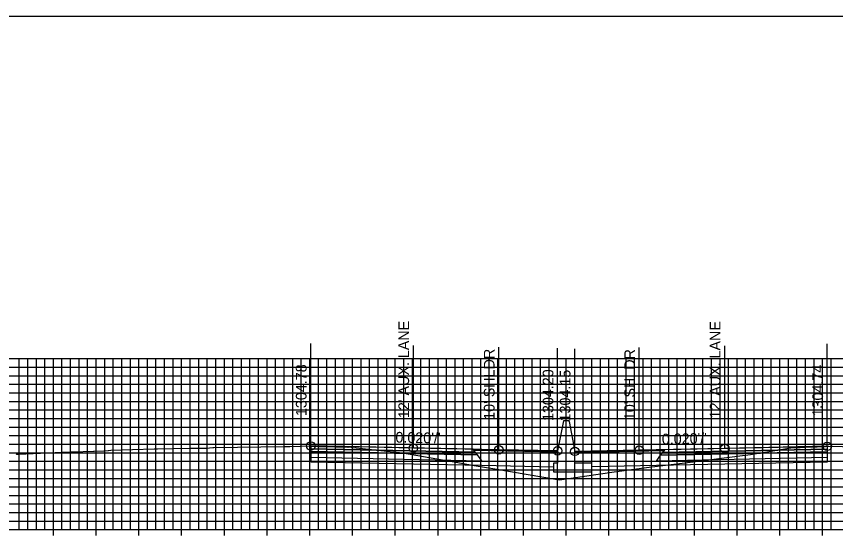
# Model space of a CAD drawing. Extents: x 674939 to 678919, y 750652 to 765176.
# Drawn here: x 678674.2 to 678770.1, y 754071.5 to 754132.6 of the extents above; entities that cross this region are included whole.
import ezdxf

# ---------------------------------------------------------------- set-up
doc = ezdxf.new("R2010")
doc.units = 0
for name, color, linetype in [('R_Alt Surface', 7, 'Continuous'), ('R_Axis', 7, 'Continuous'), ('R_Exist Surface', 7, 'Continuous'), ('R_Fin Surface', 7, 'Continuous'), ('R_Grid', 7, 'Continuous'), ('R_No Plot', 7, 'Continuous'), ('R_Proposed Road', 7, 'Continuous'), ('R_Xsect Elev', 7, 'Continuous'), ('R_Xsect Slope', 7, 'Continuous')]:
    doc.layers.add(name, color=color, linetype=linetype)

msp = doc.modelspace()

# ---------------------------------------------------------------- linework, layer by layer
at = {"layer": 'R_Alt Surface'}
for points in [[(678708.65, 754082.001), (678708.65, 754081.671), (678728.15, 754081.281), (678727.9, 754081.616)], [(678769.088, 754081.963), (678769.088, 754081.633), (678749.588, 754081.243), (678749.838, 754081.578)], [(678708.65, 754081.671), (678708.65, 754081.011), (678728.65, 754080.611), (678728.15, 754081.281)], [(678769.088, 754081.633), (678769.088, 754080.973), (678749.088, 754080.573), (678749.588, 754081.243)]]:
    msp.add_lwpolyline(points, close=True, dxfattribs=at)
for points in [[(678708.65, 754081.011), (678708.65, 754080.471), (678728.65, 754080.071), (678737.033, 754079.904)], [(678769.088, 754080.973), (678769.088, 754080.433), (678749.088, 754080.033), (678741.533, 754079.882)]]:
    msp.add_lwpolyline(points, dxfattribs=at)
at = {"layer": 'R_Axis'}
for p, q in [((678678.533, 754071.851), (678678.533, 754073.251)), ((678683.533, 754071.851), (678683.533, 754073.251)), ((678688.533, 754071.851), (678688.533, 754073.251)), ((678693.533, 754071.851), (678693.533, 754073.251)), ((678698.533, 754071.851), (678698.533, 754073.251)), ((678703.533, 754071.851), (678703.533, 754073.251)), ((678708.533, 754071.851), (678708.533, 754073.251)), ((678713.533, 754071.851), (678713.533, 754073.251)), ((678718.533, 754071.851), (678718.533, 754073.251)), ((678723.533, 754071.851), (678723.533, 754073.251)), ((678728.533, 754071.851), (678728.533, 754073.251)), ((678733.533, 754071.851), (678733.533, 754073.251)), ((678738.533, 754071.851), (678738.533, 754073.251)), ((678743.533, 754071.851), (678743.533, 754073.251)), ((678748.533, 754071.851), (678748.533, 754073.251)), ((678753.533, 754071.851), (678753.533, 754073.251)), ((678758.533, 754071.851), (678758.533, 754073.251)), ((678763.533, 754071.851), (678763.533, 754073.251)), ((678768.533, 754071.851), (678768.533, 754073.251)), ((678638.533, 754072.551), (678838.533, 754072.551))]:
    msp.add_line(p, q, dxfattribs=at)
at = {"layer": 'R_Exist Surface'}
msp.add_lwpolyline([(678674.16, 754081.354), (678674.226, 754081.365), (678674.241, 754081.368), (678674.429, 754081.376), (678680.454, 754081.652), (678680.63, 754081.66), (678680.771, 754081.664), (678683.218, 754081.741), (678683.3, 754081.742), (678684.429, 754081.765), (678684.46, 754081.768), (678684.955, 754081.807), (678684.971, 754081.809), (678685.23, 754081.829), (678690.311, 754081.983), (678690.701, 754081.994), (678694.465, 754082.064), (678694.737, 754082.069), (678696.431, 754082.096), (678696.806, 754082.1), (678697.183, 754082.142), (678697.289, 754082.147), (678705.568, 754082.275), (678706.184, 754082.285), (678708.631, 754082.332), (678708.633, 754082.332), (678708.65, 754082.331), (678708.696, 754082.329), (678709.619, 754082.272), (678709.678, 754082.271), (678710.242, 754082.262), (678710.619, 754082.283), (678711.56, 754082.235), (678711.654, 754082.234), (678712.031, 754082.243), (678712.972, 754082.21), (678713.031, 754082.207), (678713.034, 754082.208), (678713.1, 754082.228), (678713.61, 754082.17), (678719.372, 754081.542), (678725.872, 754080.384), (678727.766, 754080.054), (678730.193, 754079.647), (678737.761, 754078.367), (678743.886, 754079.266), (678747.916, 754079.81), (678752.422, 754080.379), (678760.096, 754081.337), (678763.89, 754081.954), (678765.065, 754082.149), (678765.106, 754082.141), (678765.616, 754082.173), (678765.895, 754082.163), (678766.498, 754082.185), (678767.196, 754082.218), (678767.476, 754082.21), (678767.898, 754082.222), (678768.736, 754082.257), (678768.886, 754082.266), (678769.088, 754082.293), (678769.165, 754082.303), (678769.257, 754082.308), (678772.472, 754082.252)], dxfattribs=at)
at = {"layer": 'R_Fin Surface'}
for points in [[(678737.533, 754081.754), (678730.65, 754081.891), (678720.65, 754082.091), (678708.65, 754082.331)], [(678769.088, 754082.293), (678757.088, 754082.053), (678747.088, 754081.853), (678739.533, 754081.702)]]:
    msp.add_lwpolyline(points, dxfattribs=at)
for points in [[(678708.65, 754082.331), (678708.65, 754082.001), (678727.9, 754081.616), (678727.65, 754081.951)], [(678727.65, 754081.951), (678737.533, 754081.754), (678737.537, 754081.596), (678727.769, 754081.791)], [(678749.969, 754081.753), (678739.533, 754081.544), (678739.533, 754081.702), (678750.088, 754081.913)], [(678769.088, 754082.293), (678769.088, 754081.963), (678749.838, 754081.578), (678750.088, 754081.913)]]:
    msp.add_lwpolyline(points, close=True, dxfattribs=at)
at = {"layer": 'R_Grid'}
for p, q in [((678638.533, 754092.551), (678838.533, 754092.551)), ((678674.533, 754072.551), (678674.533, 754092.551)), ((678675.533, 754072.551), (678675.533, 754092.551)), ((678676.533, 754072.551), (678676.533, 754092.551)), ((678677.533, 754072.551), (678677.533, 754092.551)), ((678678.533, 754072.551), (678678.533, 754092.551)), ((678679.533, 754072.551), (678679.533, 754092.551)), ((678680.533, 754072.551), (678680.533, 754092.551)), ((678681.533, 754072.551), (678681.533, 754092.551)), ((678682.533, 754072.551), (678682.533, 754092.551)), ((678683.533, 754072.551), (678683.533, 754092.551)), ((678684.533, 754072.551), (678684.533, 754092.551)), ((678685.533, 754072.551), (678685.533, 754092.551)), ((678686.533, 754072.551), (678686.533, 754092.551)), ((678687.533, 754072.551), (678687.533, 754092.551)), ((678688.533, 754072.551), (678688.533, 754092.551)), ((678689.533, 754072.551), (678689.533, 754092.551)), ((678690.533, 754072.551), (678690.533, 754092.551)), ((678691.533, 754072.551), (678691.533, 754092.551)), ((678692.533, 754072.551), (678692.533, 754092.551)), ((678693.533, 754072.551), (678693.533, 754092.551)), ((678694.533, 754072.551), (678694.533, 754092.551)), ((678695.533, 754072.551), (678695.533, 754092.551)), ((678696.533, 754072.551), (678696.533, 754092.551)), ((678697.533, 754072.551), (678697.533, 754092.551)), ((678698.533, 754072.551), (678698.533, 754092.551)), ((678699.533, 754072.551), (678699.533, 754092.551)), ((678700.533, 754072.551), (678700.533, 754092.551)), ((678701.533, 754072.551), (678701.533, 754092.551)), ((678702.533, 754072.551), (678702.533, 754092.551)), ((678703.533, 754072.551), (678703.533, 754092.551)), ((678704.533, 754072.551), (678704.533, 754092.551)), ((678705.533, 754072.551), (678705.533, 754092.551)), ((678706.533, 754072.551), (678706.533, 754092.551)), ((678707.533, 754072.551), (678707.533, 754092.551)), ((678708.533, 754072.551), (678708.533, 754092.551)), ((678709.533, 754072.551), (678709.533, 754092.551)), ((678710.533, 754072.551), (678710.533, 754092.551)), ((678711.533, 754072.551), (678711.533, 754092.551)), ((678712.533, 754072.551), (678712.533, 754092.551)), ((678713.533, 754072.551), (678713.533, 754092.551)), ((678714.533, 754072.551), (678714.533, 754092.551)), ((678715.533, 754072.551), (678715.533, 754092.551)), ((678716.533, 754072.551), (678716.533, 754092.551)), ((678717.533, 754072.551), (678717.533, 754092.551)), ((678718.533, 754072.551), (678718.533, 754092.551)), ((678719.533, 754072.551), (678719.533, 754092.551)), ((678720.533, 754072.551), (678720.533, 754092.551)), ((678721.533, 754072.551), (678721.533, 754092.551)), ((678722.533, 754072.551), (678722.533, 754092.551)), ((678723.533, 754072.551), (678723.533, 754092.551)), ((678724.533, 754072.551), (678724.533, 754092.551)), ((678725.533, 754072.551), (678725.533, 754092.551)), ((678726.533, 754072.551), (678726.533, 754092.551)), ((678727.533, 754072.551), (678727.533, 754092.551)), ((678728.533, 754072.551), (678728.533, 754092.551)), ((678729.533, 754072.551), (678729.533, 754092.551)), ((678730.533, 754072.551), (678730.533, 754092.551)), ((678731.533, 754072.551), (678731.533, 754092.551)), ((678732.533, 754072.551), (678732.533, 754092.551)), ((678733.533, 754072.551), (678733.533, 754092.551)), ((678734.533, 754072.551), (678734.533, 754092.551)), ((678735.533, 754072.551), (678735.533, 754092.551)), ((678736.533, 754072.551), (678736.533, 754092.551)), ((678737.533, 754072.551), (678737.533, 754092.551)), ((678738.533, 754072.551), (678738.533, 754092.551)), ((678739.533, 754072.551), (678739.533, 754092.551)), ((678740.533, 754072.551), (678740.533, 754092.551)), ((678741.533, 754072.551), (678741.533, 754092.551)), ((678742.533, 754072.551), (678742.533, 754092.551)), ((678743.533, 754072.551), (678743.533, 754092.551)), ((678744.533, 754072.551), (678744.533, 754092.551)), ((678745.533, 754072.551), (678745.533, 754092.551)), ((678746.533, 754072.551), (678746.533, 754092.551)), ((678747.533, 754072.551), (678747.533, 754092.551)), ((678748.533, 754072.551), (678748.533, 754092.551)), ((678749.533, 754072.551), (678749.533, 754092.551)), ((678750.533, 754072.551), (678750.533, 754092.551)), ((678751.533, 754072.551), (678751.533, 754092.551)), ((678752.533, 754072.551), (678752.533, 754092.551)), ((678753.533, 754072.551), (678753.533, 754092.551)), ((678754.533, 754072.551), (678754.533, 754092.551)), ((678755.533, 754072.551), (678755.533, 754092.551)), ((678756.533, 754072.551), (678756.533, 754092.551)), ((678757.533, 754072.551), (678757.533, 754092.551)), ((678758.533, 754072.551), (678758.533, 754092.551)), ((678759.533, 754072.551), (678759.533, 754092.551)), ((678760.533, 754072.551), (678760.533, 754092.551)), ((678761.533, 754072.551), (678761.533, 754092.551)), ((678762.533, 754072.551), (678762.533, 754092.551)), ((678763.533, 754072.551), (678763.533, 754092.551)), ((678764.533, 754072.551), (678764.533, 754092.551)), ((678765.533, 754072.551), (678765.533, 754092.551)), ((678766.533, 754072.551), (678766.533, 754092.551)), ((678767.533, 754072.551), (678767.533, 754092.551)), ((678768.533, 754072.551), (678768.533, 754092.551)), ((678769.533, 754072.551), (678769.533, 754092.551)), ((678638.533, 754091.551), (678838.533, 754091.551)), ((678638.533, 754090.551), (678838.533, 754090.551)), ((678638.533, 754089.551), (678838.533, 754089.551)), ((678638.533, 754088.551), (678838.533, 754088.551)), ((678638.533, 754087.551), (678838.533, 754087.551)), ((678638.533, 754086.551), (678838.533, 754086.551)), ((678638.533, 754085.551), (678838.533, 754085.551)), ((678638.533, 754084.551), (678838.533, 754084.551)), ((678638.533, 754083.551), (678838.533, 754083.551)), ((678638.533, 754082.551), (678838.533, 754082.551)), ((678638.533, 754081.551), (678838.533, 754081.551)), ((678638.533, 754080.551), (678838.533, 754080.551)), ((678638.533, 754079.551), (678838.533, 754079.551)), ((678638.533, 754078.551), (678838.533, 754078.551)), ((678638.533, 754077.551), (678838.533, 754077.551)), ((678638.533, 754076.551), (678838.533, 754076.551)), ((678638.533, 754075.551), (678838.533, 754075.551)), ((678638.533, 754074.551), (678838.533, 754074.551)), ((678638.533, 754073.551), (678838.533, 754073.551)), ((678638.533, 754072.551), (678838.533, 754072.551))]:
    msp.add_line(p, q, dxfattribs=at)
at = {"layer": 'R_No Plot'}
msp.add_lwpolyline([(678578.533, 753912.551), (678918.533, 753912.551), (678918.533, 754132.551), (678578.533, 754132.551)], close=True, dxfattribs=at)
for centre in [(678708.65, 754082.331), (678769.088, 754082.293), (678720.65, 754082.091), (678730.65, 754081.891), (678737.533, 754081.754), (678739.533, 754081.702), (678747.088, 754081.853), (678757.088, 754082.053)]:
    msp.add_circle(centre, 0.5, dxfattribs=at)
at = {"layer": 'R_Proposed Road'}
for points in [[(678738.203, 754085.254), (678737.533, 754081.754)], [(678738.863, 754085.202), (678738.863, 754085.254), (678738.203, 754085.254), (678738.203, 754085.254)], [(678738.863, 754085.202), (678739.533, 754081.702)], [(678737.533, 754081.754), (678737.533, 754080.327), (678737.033, 754080.327), (678737.033, 754079.327), (678741.533, 754079.327), (678741.533, 754080.327), (678739.533, 754080.327), (678739.533, 754081.702)]]:
    msp.add_lwpolyline(points, dxfattribs=at)
at = {"layer": 'R_Xsect Elev'}
for p, q in [((678708.65, 754082.331), (678708.65, 754094.331)), ((678769.088, 754082.293), (678769.088, 754094.293)), ((678720.65, 754082.091), (678720.65, 754094.091)), ((678730.65, 754081.891), (678730.65, 754093.891)), ((678737.533, 754081.754), (678737.533, 754093.754)), ((678739.533, 754081.702), (678739.533, 754093.702)), ((678747.088, 754081.853), (678747.088, 754093.853)), ((678757.088, 754082.053), (678757.088, 754094.053))]:
    msp.add_line(p, q, dxfattribs=at)

# ---------------------------------------------------------------- texts
for s, p in [("12' AUX. LANE", (678720.15, 754085.591)), ("12' AUX. LANE", (678756.588, 754085.553)), ("10' SHLDR", (678730.15, 754085.391)), ("10' SHLDR", (678746.588, 754085.353)), ('1304.78', (678708.15, 754085.831)), ('1304.74', (678768.588, 754085.793)), ('1304.20', (678737.033, 754085.254)), ('1304.15', (678739.033, 754085.202))]:
    msp.add_text(s, height=1.25, rotation=90, dxfattribs=at).set_placement(p)
at = {"layer": 'R_Xsect Slope'}
for rotation, p in [(358.85424, (678718.542, 754082.734)), (1.14576, (678749.737, 754082.506))]:
    msp.add_text("0.020'/'", height=1.25, rotation=rotation, dxfattribs=at).set_placement(p)

doc.saveas('drawing.dxf')
